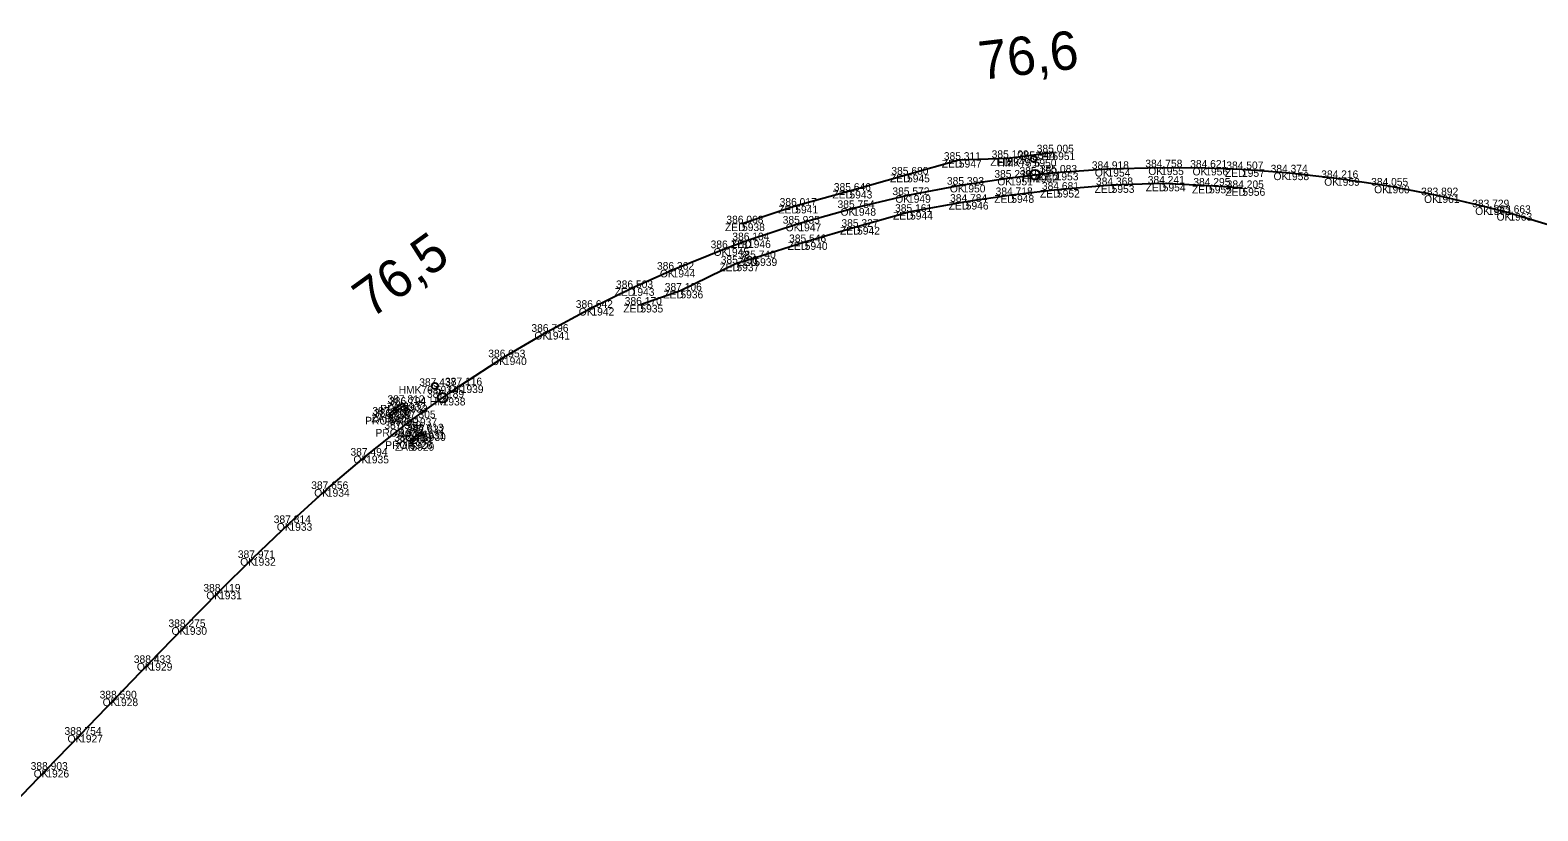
# Model space of a CAD drawing. Extents: x -621782 to -610392, y -1141853 to -1122321.
# Drawn here: x -617631.7 to -617395.9, y -1130344 to -1130221.9 of the extents above; entities that cross this region are included whole.
import ezdxf

# ---------------------------------------------------------------- set-up
doc = ezdxf.new("R2010")
doc.units = 0
for name, color, linetype in [('Vrstva 1', 7, 'Continuous'), ('Vrstva 13', 7, 'Continuous'), ('Vrstva 17', 7, 'Continuous'), ('Vrstva 19', 7, 'Continuous'), ('Vrstva 60', 7, 'Continuous'), ('Vrstva 61', 7, 'Continuous'), ('Vrstva 62', 7, 'Continuous'), ('Vrstva 7', 7, 'Continuous')]:
    doc.layers.add(name, color=color, linetype=linetype)

msp = doc.modelspace()

# ---------------------------------------------------------------- linework, layer by layer
at = {"layer": 'Vrstva 1'}
msp.add_lwpolyline([(-617635.37, -1130344.03), (-617629.19, -1130337.61), (-617623.9, -1130332.13), (-617618.4, -1130326.44), (-617613.04, -1130320.89), (-617607.62, -1130315.28), (-617602.17, -1130309.73), (-617596.87, -1130304.47), (-617591.16, -1130299), (-617585.3, -1130293.67), (-617579.16, -1130288.45), (-617573.86, -1130284.27), (-617571.63, -1130282.59), (-617567.19, -1130279.39), (-617564.36, -1130277.44), (-617557.6, -1130273.06), (-617550.84, -1130269.07), (-617543.91, -1130265.32), (-617537.62, -1130262.23), (-617531.21, -1130259.35), (-617522.82, -1130255.98), (-617519.42, -1130254.75), (-617511.54, -1130252.14), (-617502.96, -1130249.7), (-617494.39, -1130247.67), (-617485.84, -1130246.05), (-617478.43, -1130244.95), (-617474.5, -1130244.48), (-617471.29, -1130244.16), (-617463.17, -1130243.58), (-617454.8, -1130243.33), (-617447.88, -1130243.39), (-617442.14, -1130243.62), (-617435.21, -1130244.13), (-617427.28, -1130245.01), (-617419.47, -1130246.19), (-617411.67, -1130247.7), (-617403.67, -1130249.58), (-617400.31, -1130250.47), (-617392.5, -1130252.8)], dxfattribs=at)
at = {"layer": 'Vrstva 13'}
for points in [[(-617520.35, -1130252.1), (-617512.02, -1130249.34), (-617503.54, -1130247), (-617494.54, -1130244.47), (-617486.43, -1130242.16), (-617478.84, -1130241.87), (-617471.79, -1130240.99)], [(-617442.07, -1130246.58), (-617447.29, -1130246.2), (-617454.53, -1130245.88), (-617462.53, -1130246.12), (-617471.08, -1130246.85), (-617478.22, -1130247.68), (-617485.35, -1130248.73), (-617494.06, -1130250.3), (-617502.35, -1130252.65), (-617510.54, -1130255.04), (-617518.42, -1130257.56), (-617521.22, -1130258.39), (-617529.99, -1130262.63), (-617536.25, -1130264.84)]]:
    msp.add_lwpolyline(points, dxfattribs=at)
at = {"layer": 'Vrstva 17'}
for p, q in [((-617575.73, -1130282.04), (-617573.37, -1130280.2)), ((-617572.06, -1130286.48), (-617570.26, -1130284.94))]:
    msp.add_line(p, q, dxfattribs=at)
at = {"layer": 'Vrstva 19'}
for p, q in [((-617575.49, -1130282.37), (-617573.12, -1130280.5)), ((-617572.34, -1130286.19), (-617570.38, -1130284.66))]:
    msp.add_line(p, q, dxfattribs=at)
at = {"layer": 'Vrstva 60'}
for p, q in [((-617471.79, -1130240.99), (-617471.79, -1130240.99)), ((-617486.43, -1130242.16), (-617486.43, -1130242.16)), ((-617478.84, -1130241.87), (-617478.84, -1130241.87)), ((-617474.73, -1130242.03), (-617474.73, -1130242.03)), ((-617463.17, -1130243.58), (-617463.17, -1130243.58)), ((-617454.8, -1130243.33), (-617454.8, -1130243.33)), ((-617447.88, -1130243.39), (-617447.88, -1130243.39)), ((-617442.14, -1130243.62), (-617442.14, -1130243.62)), ((-617494.54, -1130244.47), (-617494.54, -1130244.47)), ((-617485.84, -1130246.05), (-617485.84, -1130246.05)), ((-617478.43, -1130244.95), (-617478.43, -1130244.95)), ((-617474.5, -1130244.48), (-617474.5, -1130244.48)), ((-617471.29, -1130244.16), (-617471.29, -1130244.16)), ((-617462.53, -1130246.12), (-617462.53, -1130246.12)), ((-617454.53, -1130245.88), (-617454.53, -1130245.88)), ((-617447.29, -1130246.2), (-617447.29, -1130246.2)), ((-617435.21, -1130244.13), (-617435.21, -1130244.13)), ((-617427.28, -1130245.01), (-617427.28, -1130245.01)), ((-617419.47, -1130246.19), (-617419.47, -1130246.19)), ((-617503.54, -1130247), (-617503.54, -1130247)), ((-617494.39, -1130247.67), (-617494.39, -1130247.67)), ((-617485.35, -1130248.73), (-617485.35, -1130248.73)), ((-617478.22, -1130247.68), (-617478.22, -1130247.68)), ((-617471.08, -1130246.85), (-617471.08, -1130246.85)), ((-617442.07, -1130246.58), (-617442.07, -1130246.58)), ((-617411.67, -1130247.7), (-617411.67, -1130247.7)), ((-617512.02, -1130249.34), (-617512.02, -1130249.34)), ((-617502.96, -1130249.7), (-617502.96, -1130249.7)), ((-617494.06, -1130250.3), (-617494.06, -1130250.3)), ((-617403.67, -1130249.58), (-617403.67, -1130249.58)), ((-617400.31, -1130250.47), (-617400.31, -1130250.47)), ((-617520.35, -1130252.1), (-617520.35, -1130252.1)), ((-617511.54, -1130252.14), (-617511.54, -1130252.14)), ((-617502.35, -1130252.65), (-617502.35, -1130252.65)), ((-617519.42, -1130254.75), (-617519.42, -1130254.75)), ((-617510.54, -1130255.04), (-617510.54, -1130255.04)), ((-617522.82, -1130255.98), (-617522.82, -1130255.98)), ((-617518.42, -1130257.56), (-617518.42, -1130257.56)), ((-617531.21, -1130259.35), (-617531.21, -1130259.35)), ((-617521.22, -1130258.39), (-617521.22, -1130258.39)), ((-617537.62, -1130262.23), (-617537.62, -1130262.23)), ((-617529.99, -1130262.63), (-617529.99, -1130262.63)), ((-617543.91, -1130265.32), (-617543.91, -1130265.32)), ((-617536.25, -1130264.84), (-617536.25, -1130264.84)), ((-617550.84, -1130269.07), (-617550.84, -1130269.07)), ((-617557.6, -1130273.06), (-617557.6, -1130273.06)), ((-617568.4, -1130277.54), (-617568.4, -1130277.54)), ((-617567.19, -1130279.39), (-617567.19, -1130279.39)), ((-617564.36, -1130277.44), (-617564.36, -1130277.44)), ((-617573.37, -1130280.2), (-617573.37, -1130280.2)), ((-617573.12, -1130280.5), (-617573.12, -1130280.5)), ((-617575.73, -1130282.04), (-617575.73, -1130282.04)), ((-617575.49, -1130282.37), (-617575.49, -1130282.37)), ((-617571.63, -1130282.59), (-617571.63, -1130282.59)), ((-617573.86, -1130284.27), (-617573.86, -1130284.27)), ((-617572.34, -1130286.19), (-617572.34, -1130286.19)), ((-617572.06, -1130286.48), (-617572.06, -1130286.48)), ((-617570.38, -1130284.66), (-617570.38, -1130284.66)), ((-617570.26, -1130284.94), (-617570.26, -1130284.94)), ((-617579.16, -1130288.45), (-617579.16, -1130288.45)), ((-617585.3, -1130293.67), (-617585.3, -1130293.67)), ((-617591.16, -1130299), (-617591.16, -1130299)), ((-617596.87, -1130304.47), (-617596.87, -1130304.47)), ((-617602.17, -1130309.73), (-617602.17, -1130309.73)), ((-617607.62, -1130315.28), (-617607.62, -1130315.28)), ((-617613.04, -1130320.89), (-617613.04, -1130320.89)), ((-617618.4, -1130326.44), (-617618.4, -1130326.44)), ((-617623.9, -1130332.13), (-617623.9, -1130332.13)), ((-617629.19, -1130337.61), (-617629.19, -1130337.61))]:
    msp.add_line(p, q, dxfattribs=at)
at = {"layer": 'Vrstva 7'}
for p, q in [((-617474.78, -1130242.04), (-617474.69, -1130242.03)), ((-617568.44, -1130277.57), (-617568.36, -1130277.51))]:
    msp.add_line(p, q, dxfattribs=at)
for centre, radius in [((-617474.73, -1130242.03), 0.5), ((-617474.5, -1130244.48), 0.75), ((-617568.4, -1130277.54), 0.5), ((-617567.19, -1130279.39), 0.75)]:
    msp.add_circle(centre, radius, dxfattribs=at)

# ---------------------------------------------------------------- texts
at = {"layer": 'Vrstva 60'}
for s, p in [('5951', (-617471.79, -1130242.19)), ('5947', (-617486.43, -1130243.36)), ('5949', (-617478.84, -1130243.07)), ('5950', (-617474.73, -1130243.23)), ('1954', (-617463.17, -1130244.78)), ('1955', (-617454.8, -1130244.53)), ('1956', (-617447.88, -1130244.59)), ('1957', (-617442.14, -1130244.82)), ('5945', (-617494.54, -1130245.67)), ('1950', (-617485.84, -1130247.25)), ('1951', (-617478.43, -1130246.15)), ('1952', (-617474.5, -1130245.68)), ('1953', (-617471.29, -1130245.36)), ('5953', (-617462.53, -1130247.32)), ('5954', (-617454.53, -1130247.08)), ('5955', (-617447.29, -1130247.4)), ('1958', (-617435.21, -1130245.33)), ('1959', (-617427.28, -1130246.21)), ('1960', (-617419.47, -1130247.39)), ('5943', (-617503.54, -1130248.2)), ('1949', (-617494.39, -1130248.87)), ('5946', (-617485.35, -1130249.93)), ('5948', (-617478.22, -1130248.88)), ('5952', (-617471.08, -1130248.05)), ('5956', (-617442.07, -1130247.78)), ('1961', (-617411.67, -1130248.9)), ('5941', (-617512.02, -1130250.54)), ('1948', (-617502.96, -1130250.9)), ('5944', (-617494.06, -1130251.5)), ('1962', (-617403.67, -1130250.78)), ('1963', (-617400.31, -1130251.67)), ('5938', (-617520.35, -1130253.3)), ('1947', (-617511.54, -1130253.34)), ('5942', (-617502.35, -1130253.85)), ('1946', (-617519.42, -1130255.95)), ('5940', (-617510.54, -1130256.24)), ('1945', (-617522.82, -1130257.18)), ('5939', (-617518.42, -1130258.76)), ('1944', (-617531.21, -1130260.55)), ('5937', (-617521.22, -1130259.58)), ('1943', (-617537.62, -1130263.43)), ('5936', (-617529.99, -1130263.83)), ('1942', (-617543.91, -1130266.52)), ('5935', (-617536.25, -1130266.04)), ('1941', (-617550.84, -1130270.27)), ('1940', (-617557.6, -1130274.27)), ('5934', (-617568.4, -1130278.74)), ('1938', (-617567.19, -1130280.59)), ('1939', (-617564.36, -1130278.64)), ('5932', (-617573.37, -1130281.4)), ('5933', (-617573.12, -1130281.7)), ('5927', (-617575.73, -1130283.24)), ('5926', (-617575.49, -1130283.57)), ('1937', (-617571.63, -1130283.79)), ('1936', (-617573.86, -1130285.47)), ('5928', (-617572.34, -1130287.39)), ('5929', (-617572.06, -1130287.68)), ('5931', (-617570.38, -1130285.86)), ('5930', (-617570.26, -1130286.14)), ('1935', (-617579.16, -1130289.65)), ('1934', (-617585.3, -1130294.87)), ('1933', (-617591.16, -1130300.2)), ('1932', (-617596.87, -1130305.67)), ('1931', (-617602.17, -1130310.93)), ('1930', (-617607.62, -1130316.48)), ('1929', (-617613.04, -1130322.09)), ('1928', (-617618.4, -1130327.64)), ('1927', (-617623.9, -1130333.33)), ('1926', (-617629.19, -1130338.81))]:
    msp.add_text(s, height=1.2, dxfattribs=at).set_placement(p)
at = {"layer": 'Vrstva 61'}
for s, p in [('385.311', (-617488.78, -1130242.16)), ('385.109', (-617481.3, -1130241.87)), ('385.344', (-617477.19, -1130242.03)), ('385.005', (-617474.25, -1130240.99)), ('385.680', (-617496.99, -1130244.47)), ('385.236', (-617480.88, -1130244.95)), ('385.150', (-617476.95, -1130244.48)), ('385.083', (-617473.74, -1130244.16)), ('384.918', (-617465.63, -1130243.58)), ('384.758', (-617457.26, -1130243.33)), ('384.621', (-617450.24, -1130243.39)), ('384.507', (-617444.59, -1130243.62)), ('384.374', (-617437.66, -1130244.13)), ('384.216', (-617429.74, -1130245.01)), ('385.646', (-617505.99, -1130247)), ('385.572', (-617496.83, -1130247.67)), ('385.393', (-617488.3, -1130246.05)), ('384.681', (-617473.44, -1130246.85)), ('384.368', (-617464.98, -1130246.12)), ('384.241', (-617456.88, -1130245.88)), ('384.295', (-617449.75, -1130246.2)), ('384.205', (-617444.52, -1130246.58)), ('384.055', (-617421.93, -1130246.19)), ('386.017', (-617514.47, -1130249.34)), ('385.754', (-617505.41, -1130249.7)), ('384.784', (-617487.8, -1130248.73)), ('384.718', (-617480.68, -1130247.68)), ('383.892', (-617414.11, -1130247.7)), ('383.729', (-617406.12, -1130249.58)), ('386.068', (-617522.8, -1130252.1)), ('385.935', (-617513.99, -1130252.14)), ('385.161', (-617496.41, -1130250.3)), ('383.663', (-617402.76, -1130250.47)), ('386.104', (-617521.87, -1130254.75)), ('385.327', (-617504.8, -1130252.65)), ('386.178', (-617525.27, -1130255.98)), ('385.546', (-617512.99, -1130255.04)), ('386.362', (-617533.66, -1130259.35)), ('385.736', (-617523.68, -1130258.39)), ('385.740', (-617520.87, -1130257.56)), ('386.503', (-617540.07, -1130262.23)), ('387.106', (-617532.44, -1130262.63)), ('386.642', (-617546.36, -1130265.32)), ('386.170', (-617538.7, -1130264.84)), ('386.796', (-617553.3, -1130269.07)), ('386.953', (-617560.05, -1130273.06)), ('387.437', (-617570.85, -1130277.54)), ('387.116', (-617566.81, -1130277.44)), ('387.812', (-617575.82, -1130280.2)), ('386.794', (-617575.57, -1130280.5)), ('387.189', (-617569.64, -1130279.39)), ('387.815', (-617578.19, -1130282.04)), ('386.800', (-617577.94, -1130282.37)), ('387.305', (-617574.09, -1130282.59)), ('387.360', (-617576.31, -1130284.27)), ('386.613', (-617572.83, -1130284.66)), ('387.632', (-617572.71, -1130284.94)), ('386.618', (-617574.79, -1130286.19)), ('387.611', (-617574.41, -1130286.48)), ('387.494', (-617581.61, -1130288.45)), ('387.656', (-617587.75, -1130293.67)), ('387.814', (-617593.61, -1130299)), ('387.971', (-617599.23, -1130304.47)), ('388.119', (-617604.62, -1130309.73)), ('388.275', (-617610.08, -1130315.28)), ('388.433', (-617615.5, -1130320.89)), ('388.590', (-617620.85, -1130326.44)), ('388.754', (-617626.35, -1130332.13)), ('388.903', (-617631.64, -1130337.61))]:
    msp.add_text(s, height=1.2, dxfattribs=at).set_placement(p)
at = {"layer": 'Vrstva 62'}
for s, p in [('ZED', (-617474.46, -1130242.19)), ('ZED', (-617489.1, -1130243.36)), ('ZED', (-617481.52, -1130243.07)), ('HMK76.6', (-617480.4, -1130243.23)), ('OK', (-617465.16, -1130244.78)), ('OK', (-617456.79, -1130244.53)), ('OK', (-617449.87, -1130244.59)), ('ZED', (-617444.81, -1130244.82)), ('ZED', (-617497.21, -1130245.67)), ('OK', (-617487.83, -1130247.25)), ('OK', (-617480.41, -1130246.15)), ('HM', (-617476.53, -1130245.68)), ('ZED', (-617473.96, -1130245.36)), ('ZED', (-617465.2, -1130247.32)), ('ZED', (-617457.2, -1130247.08)), ('ZED', (-617449.96, -1130247.4)), ('OK', (-617437.2, -1130245.33)), ('OK', (-617429.27, -1130246.21)), ('OK', (-617421.46, -1130247.39)), ('ZED', (-617506.21, -1130248.2)), ('OK', (-617496.37, -1130248.87)), ('ZED', (-617488.02, -1130249.93)), ('ZED', (-617480.9, -1130248.88)), ('ZED', (-617473.75, -1130248.05)), ('ZED', (-617444.74, -1130247.78)), ('OK', (-617413.65, -1130248.9)), ('ZED', (-617514.69, -1130250.54)), ('OK', (-617504.94, -1130250.9)), ('ZED', (-617496.73, -1130251.5)), ('OK', (-617405.65, -1130250.78)), ('OK', (-617402.3, -1130251.67)), ('ZED', (-617523.02, -1130253.3)), ('OK', (-617513.52, -1130253.34)), ('ZED', (-617505.02, -1130253.85)), ('ZED', (-617522.09, -1130255.95)), ('ZED', (-617513.21, -1130256.24)), ('OK', (-617524.8, -1130257.18)), ('ZED', (-617521.09, -1130258.76)), ('OK', (-617533.19, -1130260.55)), ('ZED', (-617523.9, -1130259.58)), ('ZED', (-617540.29, -1130263.43)), ('ZED', (-617532.66, -1130263.83)), ('OK', (-617545.89, -1130266.52)), ('ZED', (-617538.92, -1130266.04)), ('OK', (-617552.83, -1130270.27)), ('OK', (-617559.59, -1130274.27)), ('HMK76.5', (-617574.07, -1130278.74)), ('HM', (-617569.22, -1130280.59)), ('OK', (-617566.34, -1130278.64)), ('PROP', (-617576.95, -1130281.7)), ('ZAB', (-617575.97, -1130281.4)), ('PROP', (-617579.32, -1130283.57)), ('ZAB', (-617578.34, -1130283.24)), ('PROP', (-617575.47, -1130283.79)), ('PROP', (-617577.69, -1130285.47)), ('PROP', (-617576.17, -1130287.39)), ('ZAB', (-617574.66, -1130287.68)), ('PROP', (-617574.22, -1130285.86)), ('ZAB', (-617572.86, -1130286.14)), ('OK', (-617581.14, -1130289.65)), ('OK', (-617587.28, -1130294.87)), ('OK', (-617593.14, -1130300.2)), ('OK', (-617598.86, -1130305.67)), ('OK', (-617604.16, -1130310.93)), ('OK', (-617609.6, -1130316.48)), ('OK', (-617615.03, -1130322.09)), ('OK', (-617620.38, -1130327.64)), ('OK', (-617625.88, -1130333.33)), ('OK', (-617631.17, -1130338.81))]:
    msp.add_text(s, height=1.2, dxfattribs=at).set_placement(p)
at = {"layer": 'Vrstva 7'}
for s, rotation, p in [('76,6', 6.8123, (-617482.96, -1130229.66)), ('76,5', 35.7967, (-617578.39, -1130267.1))]:
    msp.add_text(s, height=6, rotation=rotation, dxfattribs=at).set_placement(p)

doc.saveas('drawing.dxf')
